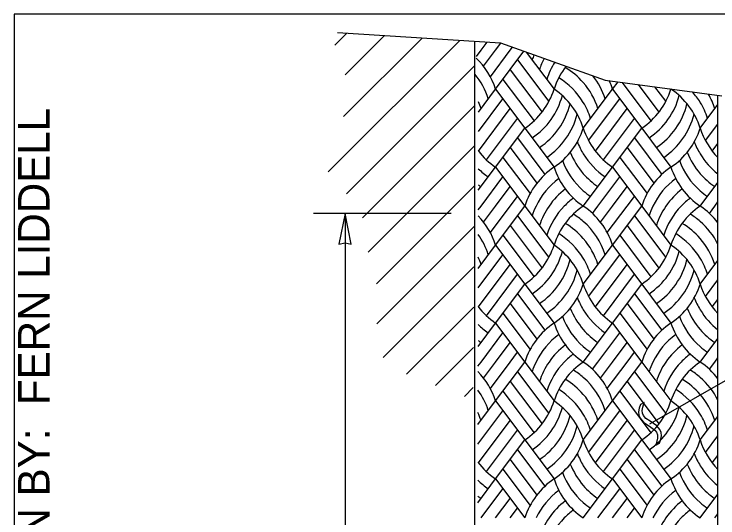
# Model space of a CAD drawing. Extents: x 99861 to 103151, y 100000 to 102076.
# Drawn here: x 99861 to 100218.6, y 101820.1 to 102076 of the extents above; entities that cross this region are included whole.
import ezdxf

# ---------------------------------------------------------------- set-up
doc = ezdxf.new("R2010")
doc.units = 0
for name, color, linetype in [('Level 1', 7, 'Continuous'), ('Level 10', 7, 'Continuous'), ('Level 15', 7, 'Continuous'), ('Level 2', 7, 'Continuous'), ('Level 3', 7, 'Continuous'), ('Level 6', 7, 'Continuous'), ('Level 62', 7, 'Continuous')]:
    doc.layers.add(name, color=color, linetype=linetype)

msp = doc.modelspace()

# ---------------------------------------------------------------- linework, layer by layer
at = {"layer": 'Level 1'}
msp.add_lwpolyline([(99861, 100000), (103150, 100000), (103150, 102076), (99861, 102076)], close=True, dxfattribs=at)
at = {"layer": 'Level 10'}
for p, q in [((100023.96, 102060.25), (100030.05, 102066.35)), ((100020.61, 101995.81), (100087.29, 102062.49)), ((100028.35, 102023.92), (100068.09, 102063.66)), ((100029.21, 102045.14), (100049.04, 102064.97)), ((100029.21, 102045.14), (100049.04, 102064.97)), ((100029.81, 101984.64), (100095.08, 102049.91)), ((100029.81, 101984.64), (100095.08, 102049.91)), ((100038.02, 101972.49), (100094.98, 102029.46)), ((100040.97, 101955.07), (100094.89, 102009)), ((100045.18, 101938.92), (100094.8, 101988.54)), ((100045.18, 101938.92), (100094.8, 101988.54)), ((100045.31, 101918.69), (100094.7, 101968.08)), ((100048.6, 101901.62), (100094.61, 101947.62)), ((100060.4, 101893.05), (100094.51, 101927.16)), ((100060.4, 101893.05), (100094.51, 101927.16)), ((100075.14, 101887.42), (100094.42, 101906.7)), ((100089.88, 101881.8), (100094.32, 101886.24))]:
    msp.add_line(p, q, dxfattribs=at)
at = {"layer": 'Level 15'}
for p, q in [((100083.13, 101974.77), (100013.13, 101974.77)), ((100029.13, 101974.77), (100029.13, 101575.23)), ((100184.08, 101867.8), (100240.37, 101900.3)), ((100179.29, 101877.63), (100178.53, 101875.8)), ((100181.12, 101878.69), (100179.29, 101877.63)), ((100180.11, 101874.67), (100180.39, 101876.38)), ((100180.39, 101876.38), (100181.12, 101878.69)), ((100178.53, 101875.8), (100178.24, 101874.03)), ((100178.24, 101874.03), (100178.43, 101872.34)), ((100180.26, 101873.31), (100180.11, 101874.67)), ((100180.76, 101872.08), (100180.26, 101873.31)), ((100178.43, 101872.34), (100179.11, 101870.71)), ((100179.11, 101870.71), (100180.86, 101868.63)), ((100182.01, 101870.62), (100180.76, 101872.08)), ((100184.1, 101869.16), (100182.01, 101870.62)), ((100187.5, 101866.89), (100184.1, 101869.16)), ((100180.86, 101868.63), (100184.48, 101866.1)), ((100184.48, 101866.1), (100186.47, 101864.72)), ((100189.05, 101864.96), (100187.5, 101866.89)), ((100186.47, 101864.72), (100187.42, 101863.56)), ((100187.42, 101863.56), (100187.9, 101862.22)), ((100187.9, 101862.22), (100187.95, 101860.57)), ((100189.69, 101863.43), (100189.05, 101864.96)), ((100189.6, 101860.07), (100189.87, 101861.83)), ((100189.87, 101861.83), (100189.69, 101863.43)), ((100187.95, 101860.57), (100187.02, 101857)), ((100188.86, 101858.05), (100189.6, 101860.07)), ((100187.03, 101857), (100188.86, 101858.05))]:
    msp.add_line(p, q, dxfattribs=at)
msp.add_lwpolyline([(100029.13, 101974.77), (100026.05, 101959.05), (100029.13, 101959.78), (100032.22, 101959.05)], close=True, dxfattribs=at)
at = {"layer": 'Level 2'}
for p, q in [((100095.13, 101575.23), (100095.13, 102062.01)), ((100218.59, 101723.57), (100218.59, 102034.68))]:
    msp.add_line(p, q, dxfattribs=at)
at = {"layer": 'Level 3'}
for p, q in [((100025.32, 102066.69), (100108.13, 102061.32)), ((100108.13, 102061.32), (100161.36, 102042.49)), ((100161.36, 102042.49), (100220.52, 102034.42))]:
    msp.add_line(p, q, dxfattribs=at)
at = {"layer": 'Level 6'}
for p, q in [((100098.23, 102057.66), (100101.3, 102061.76)), ((100105.65, 102057.66), (100108.34, 102061.24)), ((100113.08, 102057.66), (100114.21, 102059.17)), ((100095.87, 102054.51), (100098.23, 102057.66)), ((100099.54, 102049.5), (100105.65, 102057.66)), ((100102.98, 102044.2), (100113.08, 102057.66)), ((100105.65, 102037.86), (100120.07, 102057.09)), ((100121.24, 102056.68), (100135.35, 102037.86)), ((100116.79, 102052.71), (100132.68, 102031.53)), ((100113.08, 102047.76), (100129.23, 102026.22)), ((100109.37, 102042.81), (100125.16, 102021.76)), ((100165.05, 102037.86), (100167.86, 102041.6)), ((100169.87, 102041.33), (100184.55, 102021.76)), ((100096.92, 102026.21), (100105.65, 102037.86)), ((100105.65, 102037.86), (100120.5, 102018.06)), ((100150.2, 102018.06), (100165.05, 102037.86)), ((100165.05, 102037.86), (100179.9, 102018.06)), ((100178.14, 102040.2), (100188.63, 102026.22)), ((100186.41, 102039.07), (100192.07, 102031.53)), ((100194.69, 102037.94), (100194.75, 102037.86)), ((100096.9, 102016.29), (100109.37, 102032.91)), ((100152.87, 102011.73), (100168.76, 102032.91)), ((100209.6, 102018.06), (100218.59, 102030.05)), ((100096.92, 102006.42), (100113.08, 102027.96)), ((100156.32, 102006.42), (100172.47, 102027.96)), ((100101, 102001.96), (100116.79, 102023.01)), ((100160.39, 102001.96), (100176.19, 102023.01)), ((100212.27, 102011.73), (100218.59, 102020.15)), ((100105.65, 101998.26), (100120.5, 102018.06)), ((100120.5, 102018.06), (100135.35, 101998.26)), ((100165.05, 101998.26), (100179.9, 102018.06)), ((100179.9, 102018.06), (100194.75, 101998.26)), ((100116.79, 102013.11), (100130.7, 101994.57)), ((100176.19, 102013.11), (100190.09, 101994.57)), ((100215.71, 102006.42), (100218.59, 102010.26)), ((100113.08, 102008.16), (100126.62, 101990.11)), ((100172.47, 102008.16), (100186.02, 101990.11)), ((100109.37, 102003.21), (100123.18, 101984.8)), ((100168.76, 102003.21), (100182.57, 101984.8)), ((100096.85, 101986.52), (100105.65, 101998.26)), ((100105.65, 101998.26), (100120.5, 101978.46)), ((100150.2, 101978.46), (100165.05, 101998.26)), ((100165.05, 101998.26), (100179.9, 101978.46)), ((100098.23, 101978.46), (100109.37, 101993.31)), ((100157.62, 101978.46), (100168.76, 101993.31)), ((100105.65, 101978.46), (100113.08, 101988.36)), ((100165.05, 101978.46), (100172.47, 101988.36)), ((100209.6, 101978.46), (100218.59, 101990.46)), ((100113.08, 101978.46), (100116.79, 101983.41)), ((100172.47, 101978.46), (100176.19, 101983.41)), ((100217.02, 101978.46), (100218.59, 101980.56)), ((100096.83, 101976.6), (100098.23, 101978.46)), ((100099.54, 101970.31), (100105.65, 101978.46)), ((100102.98, 101965), (100113.08, 101978.46)), ((100105.65, 101958.67), (100120.5, 101978.46)), ((100120.5, 101978.46), (100135.35, 101958.67)), ((100154.85, 101974.77), (100157.62, 101978.46)), ((100158.93, 101970.31), (100165.05, 101978.46)), ((100162.37, 101965), (100172.47, 101978.46)), ((100165.05, 101958.67), (100179.9, 101978.46)), ((100179.9, 101978.46), (100194.75, 101958.67)), ((100214.25, 101974.77), (100217.02, 101978.46)), ((100116.79, 101973.51), (100132.68, 101952.33)), ((100176.19, 101973.51), (100192.07, 101952.33)), ((100218.33, 101970.31), (100218.59, 101970.66)), ((100113.08, 101968.57), (100129.23, 101947.02)), ((100172.47, 101968.57), (100188.63, 101947.02)), ((100109.37, 101963.62), (100125.16, 101942.56)), ((100168.76, 101963.62), (100184.55, 101942.56)), ((100096.78, 101946.83), (100105.65, 101958.67)), ((100105.65, 101958.67), (100120.5, 101938.87)), ((100150.2, 101938.87), (100165.05, 101958.67)), ((100165.05, 101958.67), (100179.9, 101938.87)), ((100096.76, 101936.91), (100109.37, 101953.72)), ((100152.87, 101932.53), (100168.76, 101953.72)), ((100096.92, 101927.22), (100113.08, 101948.77)), ((100156.32, 101927.22), (100172.47, 101948.77)), ((100209.6, 101938.87), (100218.59, 101950.86)), ((100101, 101922.76), (100116.79, 101943.82)), ((100160.39, 101922.76), (100176.19, 101943.82)), ((100212.27, 101932.53), (100218.59, 101940.96)), ((100105.65, 101919.07), (100120.5, 101938.87)), ((100120.5, 101938.87), (100135.35, 101919.07)), ((100165.05, 101919.07), (100179.9, 101938.87)), ((100179.9, 101938.87), (100194.75, 101919.07)), ((100116.79, 101933.92), (100130.7, 101915.37)), ((100176.19, 101933.92), (100190.09, 101915.37)), ((100215.71, 101927.22), (100218.59, 101931.06)), ((100113.08, 101928.97), (100126.62, 101910.91)), ((100172.47, 101928.97), (100186.02, 101910.91)), ((100109.37, 101924.02), (100123.18, 101905.6)), ((100168.76, 101924.02), (100182.57, 101905.6)), ((100096.71, 101907.14), (100105.65, 101919.07)), ((100105.65, 101919.07), (100120.5, 101899.27)), ((100150.2, 101899.27), (100165.05, 101919.07)), ((100165.05, 101919.07), (100179.9, 101899.27)), ((100098.23, 101899.27), (100109.37, 101914.12)), ((100157.62, 101899.27), (100168.76, 101914.12)), ((100105.65, 101899.27), (100113.08, 101909.17)), ((100165.05, 101899.27), (100172.47, 101909.17)), ((100209.6, 101899.27), (100218.59, 101911.26)), ((100113.08, 101899.27), (100116.79, 101904.22)), ((100172.47, 101899.27), (100176.19, 101904.22)), ((100217.02, 101899.27), (100218.59, 101901.36)), ((100096.69, 101897.22), (100098.23, 101899.27)), ((100099.54, 101891.11), (100105.65, 101899.27)), ((100102.98, 101885.8), (100113.08, 101899.27)), ((100105.65, 101879.47), (100120.5, 101899.27)), ((100120.5, 101899.27), (100135.35, 101879.47)), ((100154.85, 101895.57), (100157.62, 101899.27)), ((100158.93, 101891.11), (100165.05, 101899.27)), ((100162.37, 101885.8), (100172.47, 101899.27)), ((100165.05, 101879.47), (100179.9, 101899.27)), ((100179.9, 101899.27), (100194.75, 101879.47)), ((100214.25, 101895.57), (100217.02, 101899.27)), ((100116.79, 101894.32), (100132.68, 101873.14)), ((100176.19, 101894.32), (100192.07, 101873.14)), ((100218.33, 101891.11), (100218.59, 101891.46)), ((100113.08, 101889.37), (100129.23, 101867.83)), ((100172.47, 101889.37), (100188.63, 101867.83)), ((100109.37, 101884.42), (100125.16, 101863.36)), ((100168.76, 101884.42), (100184.55, 101863.36)), ((100096.64, 101867.45), (100105.65, 101879.47)), ((100105.65, 101879.47), (100120.5, 101859.67)), ((100150.2, 101859.67), (100165.05, 101879.47)), ((100165.05, 101879.47), (100179.9, 101859.67)), ((100096.62, 101857.52), (100109.37, 101874.52)), ((100152.87, 101853.34), (100168.76, 101874.52)), ((100096.92, 101848.03), (100113.08, 101869.57)), ((100156.32, 101848.03), (100172.47, 101869.57)), ((100209.6, 101859.67), (100218.59, 101871.66)), ((100101, 101843.57), (100116.79, 101864.62)), ((100160.39, 101843.57), (100176.19, 101864.62)), ((100212.27, 101853.34), (100218.59, 101861.76)), ((100105.65, 101839.87), (100120.5, 101859.67)), ((100120.5, 101859.67), (100135.35, 101839.87)), ((100165.05, 101839.87), (100179.9, 101859.67)), ((100179.9, 101859.67), (100194.75, 101839.87)), ((100116.79, 101854.72), (100130.7, 101836.18)), ((100176.19, 101854.72), (100190.09, 101836.18)), ((100215.71, 101848.03), (100218.59, 101851.86)), ((100113.08, 101849.77), (100126.62, 101831.71)), ((100172.47, 101849.77), (100186.02, 101831.71)), ((100109.37, 101844.82), (100123.18, 101826.41)), ((100168.76, 101844.82), (100182.57, 101826.41)), ((100096.56, 101827.75), (100105.65, 101839.87)), ((100105.65, 101839.87), (100120.5, 101820.07)), ((100150.2, 101820.07), (100165.05, 101839.87)), ((100165.05, 101839.87), (100179.9, 101820.07)), ((100098.23, 101820.07), (100109.37, 101834.92)), ((100157.62, 101820.07), (100168.76, 101834.92)), ((100105.65, 101820.07), (100113.08, 101829.97)), ((100165.05, 101820.07), (100172.47, 101829.97)), ((100209.6, 101820.07), (100218.59, 101832.06)), ((100113.08, 101820.07), (100116.79, 101825.02)), ((100172.47, 101820.07), (100176.19, 101825.02)), ((100217.02, 101820.07), (100218.59, 101822.16))]:
    msp.add_line(p, q, dxfattribs=at)
for centre, start, end in [((100160.02, 102041.32), 158.1646, 162.3566), ((100069.84, 102026.47), 17.6434, 46.3052), ((100163.74, 102036.37), 152.9148, 162.3566), ((100167.45, 102031.42), 147.5997, 162.3566), ((100171.16, 102026.47), 142.1685, 162.3566), ((100121.82, 102016.57), 40.9413, 59.3021), ((100066.13, 102021.52), 17.6434, 39.4801), ((100125.53, 102021.52), 17.6434, 38.089), ((100118.1, 102011.62), 31.3316, 58.4874), ((100121.81, 102016.57), 17.6434, 40.9414), ((100129.24, 102026.47), 17.6434, 24.772), ((100099.54, 102049.25), 303.9036, 342.3566), ((100114.39, 102006.67), 17.6434, 56.0964), ((100158.94, 102049.25), 303.9036, 342.3566), ((100230.56, 102026.47), 162.2434, 162.3566), ((100173.79, 102006.67), 17.6434, 56.0964), ((100103.25, 102044.3), 303.9036, 345.0113), ((100162.65, 102044.3), 303.9036, 345.0113), ((100177.5, 102011.62), 31.3316, 41.3303), ((100181.21, 102016.57), 17.6434, 29.9641), ((100062.42, 102016.57), 17.6434, 23.3182), ((100106.97, 102039.35), 303.9036, 346.3199), ((100118.1, 102011.62), 17.6434, 31.3317), ((100166.36, 102039.35), 303.9036, 346.3199), ((100177.5, 102011.62), 17.6434, 31.3317), ((100110.68, 102034.4), 303.9036, 345.7713), ((100170.07, 102034.4), 303.9036, 345.7713), ((100114.39, 102029.45), 303.9036, 342.3566), ((100186.01, 102029.45), 197.6435, 236.0964), ((100173.79, 102029.45), 303.9036, 342.3566), ((100245.41, 102029.45), 197.6435, 224.4692), ((100182.3, 102024.5), 200.8778, 211.332), ((100241.69, 102024.5), 200.8778, 211.332), ((100126.61, 102029.45), 217.7021, 236.0964), ((100178.59, 102019.55), 201.4344, 220.9416), ((100182.3, 102024.5), 211.3319, 236.0964), ((100237.98, 102019.55), 201.4344, 220.9416), ((100241.69, 102024.5), 211.3319, 232.06), ((100174.87, 102014.6), 200.2432, 228.9599), ((100234.27, 102014.6), 200.2432, 228.9599), ((100156.31, 101967.08), 123.9036, 162.3566), ((100171.16, 102009.65), 197.6434, 236.0964), ((100215.71, 101967.08), 123.9036, 162.3566), ((100230.56, 102009.65), 197.6434, 236.0964), ((100122.9, 102024.5), 226.1448, 236.0964), ((100178.58, 102019.55), 220.9415, 236.0964), ((100237.98, 102019.55), 220.9415, 236.0964), ((100160.02, 101962.13), 126.3063, 154.2266), ((100219.42, 101962.13), 126.3063, 154.2266), ((100119.19, 102019.55), 233.5281, 236.0964), ((100163.74, 101957.18), 127.1006, 145.4911), ((100223.13, 101957.18), 127.1006, 145.4911), ((100174.87, 102014.6), 228.9599, 236.0964), ((100234.27, 102014.6), 228.9599, 236.0964), ((100167.45, 101952.23), 126.331, 135.7128), ((100226.85, 101952.23), 126.331, 135.7128), ((100160.02, 101962.13), 154.2265, 162.3566), ((100163.74, 101957.18), 145.491, 162.3566), ((100167.45, 101952.23), 135.7127, 162.3566), ((100171.16, 101947.28), 123.9036, 162.3566), ((100129.24, 101947.28), 17.6434, 56.0963), ((100219.42, 101962.13), 154.2265, 162.3566), ((100223.13, 101957.18), 145.491, 162.3566), ((100226.85, 101952.23), 135.7127, 162.3566), ((100230.56, 101947.28), 123.9036, 162.3566), ((100188.64, 101947.28), 37.1429, 56.0963), ((100069.84, 101947.28), 17.6434, 44.1107), ((100125.53, 101942.33), 48.9597, 58.5465), ((100184.92, 101942.33), 48.9597, 58.5465), ((100121.82, 101937.38), 40.9413, 59.3021), ((100125.53, 101942.33), 17.6434, 48.9597), ((100181.21, 101937.38), 40.9413, 59.3021), ((100184.92, 101942.33), 26.3728, 48.9597), ((100066.13, 101942.33), 17.6434, 35.2796), ((100118.1, 101932.43), 31.3316, 58.4874), ((100121.81, 101937.38), 17.6434, 40.9414), ((100177.5, 101932.43), 31.3316, 58.4874), ((100181.21, 101937.38), 17.6434, 40.9414), ((100099.54, 101970.06), 303.9036, 342.3566), ((100114.39, 101927.48), 17.6434, 56.0964), ((100158.94, 101970.06), 303.9036, 342.3566), ((100173.79, 101927.48), 17.6434, 56.0964), ((100103.25, 101965.11), 303.9036, 345.0113), ((100162.65, 101965.11), 303.9036, 345.0113), ((100062.42, 101937.38), 17.6434, 23.8521), ((100106.97, 101960.16), 303.9036, 346.3199), ((100118.1, 101932.43), 17.6434, 31.3317), ((100166.36, 101960.16), 303.9036, 346.3199), ((100177.5, 101932.43), 17.6434, 31.3317), ((100110.68, 101955.21), 303.9036, 345.7713), ((100170.07, 101955.21), 303.9036, 345.7713), ((100114.39, 101950.26), 303.9036, 342.3566), ((100186.01, 101950.26), 197.6435, 236.0964), ((100173.79, 101950.26), 303.9036, 342.3566), ((100245.41, 101950.26), 197.6435, 224.4692), ((100182.3, 101945.31), 200.8778, 211.332), ((100241.69, 101945.31), 200.8778, 211.332), ((100126.61, 101950.26), 217.3508, 236.0964), ((100178.59, 101940.36), 201.4344, 220.9416), ((100237.98, 101940.36), 201.4344, 220.9416), ((100182.3, 101945.31), 211.3319, 236.0964), ((100241.69, 101945.31), 211.3319, 232.06), ((100156.31, 101887.88), 123.9036, 162.3566), ((100171.16, 101930.46), 197.6434, 236.0964), ((100174.87, 101935.41), 200.2432, 228.9599), ((100215.71, 101887.88), 123.9036, 162.3566), ((100230.56, 101930.46), 197.6434, 236.0964), ((100234.27, 101935.41), 200.2432, 228.9599), ((100122.9, 101945.31), 225.8471, 236.0964), ((100178.58, 101940.36), 220.9415, 236.0964), ((100237.98, 101940.36), 220.9415, 236.0964), ((100160.02, 101882.93), 126.3063, 154.2266), ((100219.42, 101882.93), 126.3063, 154.2266), ((100119.19, 101940.36), 233.2613, 236.0964), ((100163.74, 101877.98), 127.1006, 145.4911), ((100174.87, 101935.41), 228.9599, 236.0964), ((100223.13, 101877.98), 127.1006, 145.4911), ((100234.27, 101935.41), 228.9599, 236.0964), ((100167.45, 101873.03), 126.331, 135.7128), ((100226.85, 101873.03), 126.331, 135.7128), ((100160.02, 101882.93), 154.2265, 162.3566), ((100163.74, 101877.98), 145.491, 162.3566), ((100167.45, 101873.03), 135.7127, 162.3566), ((100171.16, 101868.08), 123.9036, 162.3566), ((100129.24, 101868.08), 17.6434, 56.0963), ((100219.42, 101882.93), 154.2265, 162.3566), ((100223.13, 101877.98), 145.491, 162.3566), ((100226.85, 101873.03), 135.7127, 162.3566), ((100230.56, 101868.08), 123.9036, 162.3566), ((100188.64, 101868.08), 37.1429, 56.0963), ((100069.84, 101868.08), 17.6434, 44.4174), ((100125.53, 101863.13), 48.9597, 58.5465), ((100184.92, 101863.13), 48.9597, 58.5465), ((100121.82, 101858.18), 40.9413, 59.3021), ((100125.53, 101863.13), 17.6434, 48.9597), ((100181.21, 101858.18), 40.9413, 59.3021), ((100184.92, 101863.13), 26.3728, 48.9597), ((100066.13, 101863.13), 17.6434, 35.6484), ((100118.1, 101853.23), 31.3316, 58.4874), ((100177.5, 101853.23), 31.3316, 58.4874), ((100121.81, 101858.18), 17.6434, 40.9414), ((100181.21, 101858.18), 17.6434, 40.9414), ((100099.54, 101890.86), 303.9036, 342.3566), ((100103.25, 101885.91), 303.9036, 345.0113), ((100114.39, 101848.28), 17.6434, 56.0964), ((100158.94, 101890.86), 303.9036, 342.3566), ((100162.65, 101885.91), 303.9036, 345.0113), ((100173.79, 101848.28), 17.6434, 56.0964), ((100062.42, 101858.18), 17.6434, 24.375), ((100118.1, 101853.23), 17.6434, 31.3317), ((100177.5, 101853.23), 17.6434, 31.3317), ((100106.97, 101880.96), 303.9036, 346.3199), ((100166.36, 101880.96), 303.9036, 346.3199), ((100110.68, 101876.01), 303.9036, 345.7713), ((100170.07, 101876.01), 303.9036, 345.7713), ((100114.39, 101871.06), 303.9036, 342.3566), ((100186.01, 101871.06), 197.6435, 236.0964), ((100173.79, 101871.06), 303.9036, 342.3566), ((100245.41, 101871.06), 197.6435, 224.4692), ((100182.3, 101866.11), 200.8778, 211.332), ((100241.69, 101866.11), 200.8778, 211.332), ((100126.61, 101871.06), 216.9967, 236.0964), ((100178.59, 101861.16), 201.4344, 220.9416), ((100182.3, 101866.11), 211.3319, 236.0964), ((100237.98, 101861.16), 201.4344, 220.9416), ((100241.69, 101866.11), 211.3319, 232.06), ((100174.87, 101856.21), 200.2432, 228.9599), ((100234.27, 101856.21), 200.2432, 228.9599), ((100122.9, 101866.11), 225.548, 236.0964), ((100156.31, 101808.68), 123.9036, 162.3566), ((100171.16, 101851.26), 197.6434, 236.0964), ((100215.71, 101808.68), 123.9036, 162.3566), ((100230.56, 101851.26), 197.6434, 236.0964), ((100160.02, 101803.73), 126.3063, 154.2266), ((100178.58, 101861.16), 220.9415, 236.0964), ((100219.42, 101803.73), 126.3063, 154.2266), ((100237.98, 101861.16), 220.9415, 236.0964), ((100119.19, 101861.16), 232.9935, 236.0964), ((100163.74, 101798.78), 127.1006, 145.4911), ((100174.87, 101856.21), 228.9599, 236.0964), ((100223.13, 101798.78), 127.1006, 145.4911), ((100234.27, 101856.21), 228.9599, 236.0964), ((100167.45, 101793.83), 126.331, 135.7128), ((100226.85, 101793.83), 126.331, 135.7128), ((100163.74, 101798.78), 145.491, 162.3566), ((100167.45, 101793.83), 135.7127, 162.3566), ((100223.13, 101798.78), 145.491, 162.3566), ((100226.85, 101793.83), 135.7127, 162.3566)]:
    msp.add_arc(centre, 37.58, start, end, dxfattribs=at)

# ---------------------------------------------------------------- texts
at = {"layer": 'Level 62'}
msp.add_text('DRAWN BY:  FERN LIDDELL', height=16, rotation=90, dxfattribs=at).set_placement((99879, 101744.22))

doc.saveas('drawing.dxf')
